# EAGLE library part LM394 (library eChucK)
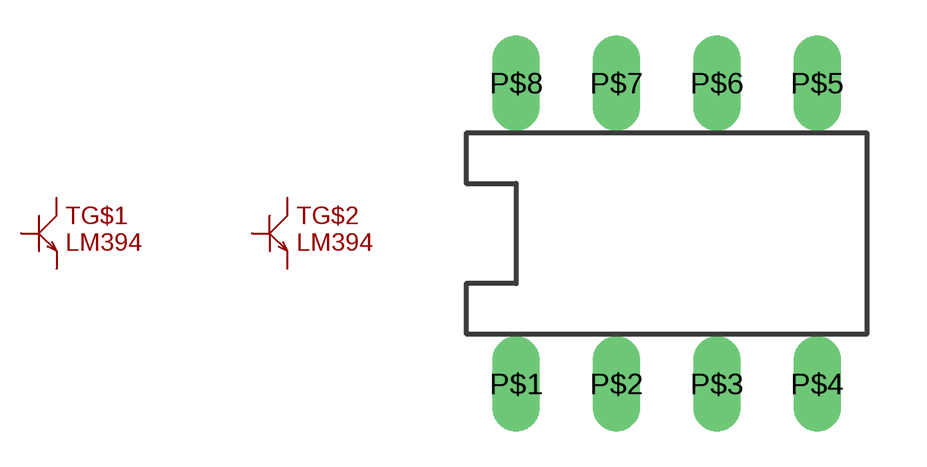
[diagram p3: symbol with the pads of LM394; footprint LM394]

Designator prefix T; gates G$1=LM394A G$2=LM394B

## LM394  [LM394]
P$1  G$1:P$1
P$2  G$1:P$2
P$3  G$1:P$3
P$6  G$2:P$6
P$7  G$2:P$7
P$8  G$2:P$8

## Footprint LM394 (pad centres in mm)
drill 0.7 long: P$1 -3.81,-3.81; P$2 -1.27,-3.81; P$3 1.27,-3.81; P$4 3.81,-3.81; P$5 3.81,3.81; P$6 1.27,3.81; P$7 -1.27,3.81; P$8 -3.81,3.81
